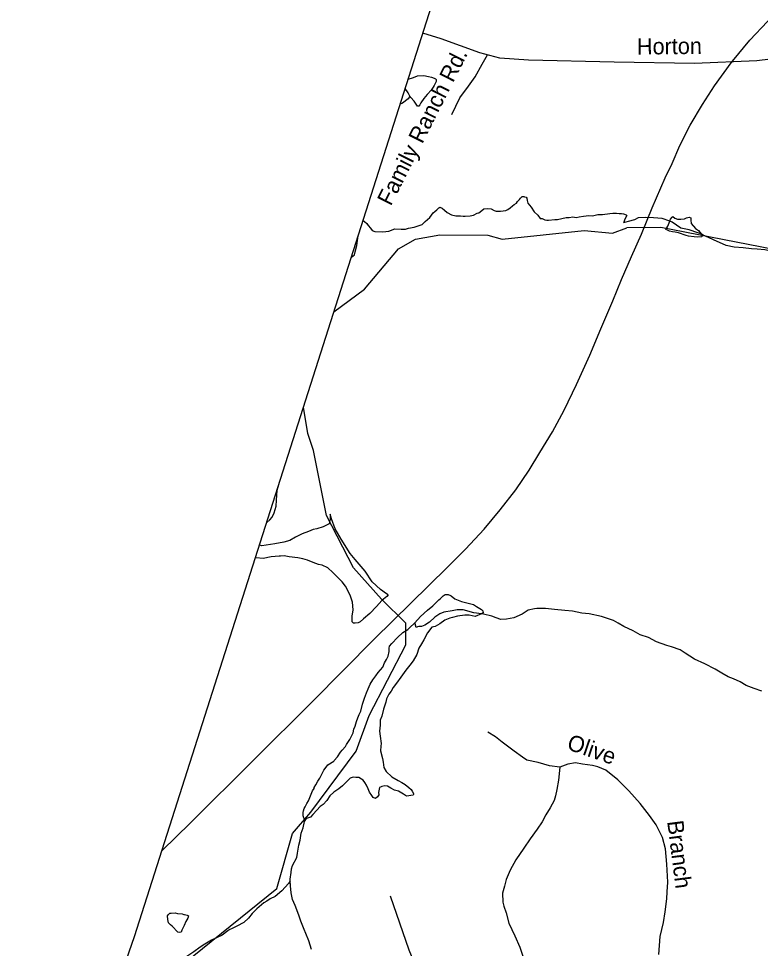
# Model space of a CAD drawing. Extents: x 2001466 to 2224147, y 644118 to 847247.
# Drawn here: x 2006818 to 2011176, y 697641 to 703106 of the extents above; entities that cross this region are included whole.
import ezdxf

# ---------------------------------------------------------------- set-up
doc = ezdxf.new("R2010")
doc.units = 0
for name, color, linetype in [('Exist Boundary Political CountyLine', 7, 'Continuous'), ('Exist Hydrographic Misc Water Feature', 7, 'Continuous'), ('Exist Railroad Mainline', 7, 'Continuous'), ('Exist Road Non-System Type 51', 7, 'Continuous'), ('Exist Road Non-System Type 51 Label', 7, 'Continuous'), ('Exist Road Secondary Type 51 Attributed', 7, 'Continuous'), ('Exist Road Secondary Type 51 Label', 7, 'Continuous')]:
    doc.layers.add(name, color=color, linetype=linetype)

msp = doc.modelspace()

# ---------------------------------------------------------------- linework, layer by layer
at = {"layer": 'Exist Boundary Political CountyLine'}
msp.add_lwpolyline([(2006817.6, 695750.4), (2007499.4, 697710.6), (2010412.6, 706844.6), (2011918.3, 711705.5), (2013748.8, 717730), (2014941.8, 722041.3), (2015284.7, 723238.9), (2015749.8, 724659.3), (2016152.8, 726117.8), (2016501.7, 727373.6), (2016860.6, 728619.5), (2017411.9, 730567.4), (2017756.8, 731851.4), (2018083.6, 732956.8), (2018350.2, 733869.6), (2018833.4, 735584.8), (2018918.2, 735898.3), (2019734.3, 740137.7), (2020502.6, 744108.1), (2021805.5, 746807.9), (2022821.6, 749625), (2023527, 751602.5)], dxfattribs=at)
at = {"layer": 'Exist Hydrographic Misc Water Feature'}
for p, q in [((2010307.7, 701844.5), (2010390.7, 701875.6)), ((2009092.7, 699552.7), (2008950.6, 699693.4))]:
    msp.add_line(p, q, dxfattribs=at)
for points in [[(2009106.6, 702749.8), (2009136.8, 702759.4), (2009160.8, 702769.4), (2009198.7, 702771.4), (2009224.8, 702765.5), (2009242.8, 702761.5), (2009258.8, 702755.5), (2009266.8, 702751.5), (2009270.7, 702747.5), (2009270.7, 702735.5), (2009258.8, 702713.5), (2009242.8, 702687.5), (2009218.8, 702659.5), (2009198.9, 702635.4), (2009180.9, 702611.5), (2009175, 702599.4), (2009168.8, 702591.4), (2009160.8, 702591.4), (2009140.9, 702621.4), (2009122.9, 702641.4), (2009116.9, 702649.4)], [(2009116.9, 702649.4), (2009106.9, 702669.5), (2009089.3, 702695.6)], [(2009116.9, 702649.4), (2009106.9, 702633.4), (2009072.8, 702609.4), (2009059.9, 702603.5)], [(2014407.7, 701337.8), (2014532.8, 701745.4), (2014532.8, 701896.4), (2014490.7, 701989), (2014390.7, 702096.1), (2014148.7, 702153.5), (2013665.6, 702120.7), (2013198.7, 702304.1), (2012782.6, 702260.1), (2012598.7, 702368.8), (2012440.6, 702345.7), (2012332.8, 702302.1), (2012082.8, 702103.7), (2011815.6, 702036.9), (2011507.6, 701793.8), (2011324.7, 701735.2), (2010590.6, 701878.2), (2010390.7, 701875.6)], [(2008841.7, 701919.2), (2008849.3, 701913.3), (2008863.3, 701901.3), (2008871.3, 701889.4), (2008885.4, 701873.3), (2008895.3, 701861.3), (2008911.3, 701855.3), (2008957.4, 701853.5), (2008993.3, 701857.4), (2009027.3, 701869.4), (2009065.2, 701867.4), (2009091.3, 701867.5), (2009107.3, 701873.5), (2009141.3, 701879.5), (2009189.3, 701895.5), (2009207.1, 701913.6), (2009233.2, 701937.6), (2009253.3, 701963.6), (2009263.1, 701971.6), (2009275.2, 701981.6), (2009279.1, 701985.6), (2009287.1, 701993.6), (2009293.3, 701997.6), (2009305.2, 701991.6), (2009319.3, 701979.6), (2009335.3, 701965.6), (2009361.1, 701951.6), (2009387.2, 701945.7), (2009413.2, 701945.7), (2009429.2, 701943.7), (2009441.1, 701943.7), (2009471.3, 701945.8), (2009489.3, 701949.8), (2009511.2, 701961.8), (2009521.3, 701963.8), (2009539.1, 701977.8), (2009551.2, 701987.8), (2009573.2, 701989.8), (2009593.3, 701987.8), (2009611.3, 701977.8), (2009623.2, 701973.8), (2009649, 701973.8), (2009679.2, 701977.8), (2009691.3, 701983.8), (2009705, 701993.9), (2009719.2, 702005.9), (2009729, 702013.9), (2009743.2, 702021.9), (2009749.1, 702029.9), (2009753, 702033.9), (2009761, 702041.9), (2009767.1, 702049.9), (2009771, 702053.9), (2009777, 702059.9), (2009785.2, 702059.9), (2009789.1, 702057.9), (2009799.1, 702055.9), (2009803, 702049.9), (2009805.1, 702035.9), (2009809.2, 702022), (2009829.1, 701998), (2009847.1, 701969.9), (2009867.2, 701949.9), (2009881.2, 701931.9), (2009893.2, 701930), (2009909, 701924), (2009921.1, 701922), (2009931.2, 701922), (2009967.3, 701926), (2009983.1, 701926), (2010009.1, 701930.1), (2010035.1, 701936.1), (2010043.1, 701936.1), (2010053, 701936.1), (2010073.1, 701940.1), (2010093.2, 701936.1), (2010111, 701940.1), (2010137.1, 701944.1), (2010167, 701948.1), (2010189.1, 701946.2), (2010221.1, 701954.2), (2010247.2, 701954.2), (2010291, 701960.2), (2010309.1, 701962.3), (2010331, 701962.3), (2010345, 701960.3), (2010359.1, 701960.3), (2010371, 701958.3), (2010387, 701952.3), (2010391.1, 701948.3), (2010381.1, 701930.2), (2010371, 701906.3)], [(2010643.1, 701914.5), (2010599, 701930.4), (2010547.2, 701934.4), (2010503.1, 701936.4), (2010457.1, 701934.3), (2010437, 701922.3), (2010399.1, 701912.4), (2010371, 701906.3)], [(2010643.1, 701914.5), (2010647, 701926.4), (2010657.1, 701938.4), (2010661.2, 701942.4), (2010673.1, 701932.4), (2010689.1, 701926.4), (2010709.2, 701926.5), (2010729, 701928.4), (2010741.1, 701934.5), (2010749.1, 701936.5), (2010757.1, 701938.5), (2010767, 701934.5), (2010767, 701920.5), (2010769, 701902.5), (2010795.1, 701872.5), (2010811.1, 701860.6), (2010819.1, 701850.6), (2010829.1, 701838.6)], [(2010829.1, 701838.6), (2010831.2, 701830.6), (2010831.2, 701822.6), (2010809, 701820.5), (2010787.1, 701822.5), (2010753, 701826.5), (2010739.1, 701830.5), (2010695, 701846.5), (2010675.1, 701850.5), (2010659.1, 701852.5), (2010641.1, 701856.5), (2010629, 701862.5), (2010621, 701866.5), (2010631, 701886.5), (2010643.1, 701914.5)], [(2010829.1, 701838.6), (2010807.2, 701846.5), (2010757.1, 701864.5), (2010709.2, 701874.5), (2010683.1, 701892.5), (2010657.1, 701908.5), (2010643.1, 701914.5)], [(2008670.3, 701382), (2008849.7, 701516.5), (2009049.7, 701752), (2009149.7, 701809), (2009291.6, 701835.7), (2009574.8, 701833.2), (2009657.6, 701808.5), (2010140.7, 701861), (2010307.7, 701844.5)], [(2008771.6, 701699.4), (2008781.5, 701709.3), (2008791.5, 701717.3), (2008795.4, 701735.3), (2008805.2, 701771.3), (2008809.3, 701801.3), (2008813.1, 701829.6)], [(2011523, 701743), (2011517.1, 701743), (2011459, 701739), (2011405.1, 701740.9), (2011357.1, 701740.9), (2011329, 701736.9), (2011279, 701732.8), (2011247, 701736.8), (2011201.1, 701746.8), (2011157, 701750.8), (2011123.2, 701752.8), (2011075, 701758.7), (2011021, 701762.7), (2010975.1, 701772.7), (2010901.1, 701804.6), (2010871.1, 701818.6), (2010839.2, 701832.6), (2010829.1, 701838.6)], [(2008950.6, 699693.4), (2008784.7, 699877.3), (2008625.6, 700185.7), (2008550.8, 700567.8), (2008516.7, 700666.9), (2008491.7, 700821.9)], [(2008275.5, 700144.1), (2008294.5, 700159.2), (2008306.4, 700175.1), (2008318.4, 700201.1), (2008330.3, 700239.2), (2008332.4, 700275.2), (2008334.2, 700303.2), (2008336.1, 700334), (2008340.3, 700347.3), (2008344, 700358.7)], [(2008648.4, 700193.4), (2008648.4, 700163.4), (2008642.2, 700135.4), (2008606.3, 700119.4), (2008570.5, 700107.3), (2008548.3, 700103.3), (2008520.4, 700091.3), (2008484.3, 700077.3), (2008444.4, 700057.3), (2008410.3, 700039.3), (2008376.5, 700029.2), (2008322.3, 700019.2), (2008246.5, 700007.2), (2008232.8, 700010.3)], [(2008988.6, 699719.7), (2008978.5, 699725.7), (2008944.5, 699749.7), (2008894.4, 699795.6), (2008854.5, 699857.5), (2008794.4, 699927.5), (2008766.5, 699961.5), (2008712.4, 700045.4), (2008678.3, 700107.4), (2008656.4, 700165.4), (2008648.4, 700193.4)], [(2008988.6, 699719.7), (2008980.6, 699709.7), (2008952.5, 699685.6), (2008920.5, 699649.6), (2008880.7, 699609.6), (2008844.6, 699577.6), (2008824.7, 699559.6), (2008812.6, 699553.5), (2008794.6, 699551.5), (2008784.7, 699551.5), (2008776.7, 699559.5), (2008776.7, 699593.5), (2008782.7, 699631.6), (2008778.6, 699675.5), (2008766.5, 699717.5), (2008756.4, 699735.5), (2008748.4, 699751.5), (2008738.6, 699769.5), (2008718.5, 699795.5), (2008688.6, 699825.5), (2008664.6, 699849.4), (2008634.4, 699877.4), (2008600.6, 699893.4), (2008580.5, 699897.4), (2008548.5, 699909.4), (2008514.5, 699923.3), (2008488.4, 699931.3), (2008458.5, 699937.3), (2008406.6, 699943.3), (2008378.5, 699947.3), (2008356.6, 699947.2), (2008348.6, 699947.2), (2008300.6, 699943.2), (2008254.5, 699933.1), (2008212.4, 699937.1)], [(2009144.6, 699553.8), (2009178.6, 699591.8), (2009220.5, 699629.8), (2009250.6, 699653.9), (2009270.5, 699673.8), (2009286.5, 699689.8), (2009296.5, 699697.8), (2009312.5, 699713.9), (2009324.4, 699721.9), (2009340.4, 699721.9), (2009354.6, 699715.9), (2009358.5, 699713.9), (2009380.6, 699695.9), (2009420.6, 699679.9), (2009458.5, 699670), (2009490.5, 699662), (2009508.6, 699650), (2009526.6, 699638), (2009536.5, 699632), (2009544.5, 699624.1), (2009546.5, 699614), (2009536.5, 699608)], [(2011184.7, 699153.1), (2011138.5, 699169.1), (2011092.6, 699187), (2011056.7, 699207), (2011018.6, 699224.9), (2010986.6, 699236.9), (2010948.7, 699259), (2010910.7, 699282.9), (2010848.6, 699312.9), (2010788.5, 699340.8), (2010734.6, 699376.8), (2010704.4, 699394.8), (2010652.6, 699412.7), (2010626.5, 699420.8), (2010564.6, 699442.7), (2010518.5, 699468.6), (2010468.4, 699484.6), (2010428.4, 699506.6), (2010372.5, 699532.6), (2010340.5, 699552.5), (2010312.6, 699568.5), (2010242.5, 699592.5), (2010170.5, 699606.4), (2010126.6, 699610.4), (2010072.5, 699622.4), (2010026.5, 699626.3), (2009966.5, 699632.3), (2009912.5, 699638.3), (2009862.5, 699638.2), (2009848.5, 699636.3), (2009810.6, 699628.2), (2009776.6, 699606.2), (2009726.5, 699584.1), (2009684.5, 699576.1), (2009650.5, 699574.1), (2009622.6, 699584), (2009598.6, 699594), (2009548.6, 699606.1), (2009536.5, 699608)], [(2009536.5, 699608), (2009500.6, 699592), (2009464.5, 699600), (2009438.4, 699599.9), (2009396.6, 699593.9), (2009366.5, 699585.9), (2009350.5, 699581.9), (2009322.6, 699569.9), (2009292.7, 699547.8), (2009264.6, 699533.8), (2009244.7, 699529.9), (2009220.7, 699495.9), (2009198.7, 699453.8), (2009184.6, 699431.8), (2009168.8, 699405.8), (2009156.7, 699367.8), (2009134.8, 699331.8), (2009116.7, 699305.8), (2009092.7, 699275.8), (2009082.7, 699261.8), (2009062.8, 699235.8), (2009037, 699199.7), (2009018.9, 699173.7), (2009006.8, 699153.7), (2008992.9, 699135.7), (2008978.9, 699107.8), (2008974.8, 699087.7), (2008960.9, 699047.7), (2008951, 699005.7), (2008941, 698981.7), (2008941, 698953.7), (2008937.1, 698917.7), (2008941, 698887.7), (2008947.1, 698845.7), (2008945.1, 698829.8), (2008943, 698801.7), (2008955.1, 698757.7), (2008959, 698735.8), (2008963.1, 698703.7), (2008977.1, 698679.8), (2009011.1, 698649.8), (2009047.2, 698627.9), (2009069.1, 698615.8), (2009089, 698603.8), (2009111.2, 698585.8), (2009123.1, 698575.8), (2009129.2, 698565.9), (2009137.2, 698551.9), (2009137.2, 698545.9), (2009135.2, 698541.9), (2009097.2, 698535.9), (2009079.2, 698547.9), (2009049.3, 698565.9), (2009025.3, 698571.8), (2009005.2, 698581.8), (2008985.3, 698593.8), (2008969.3, 698595.8), (2008951.2, 698591.7), (2008947.1, 698589.8), (2008937.3, 698585.8), (2008931.1, 698557.8), (2008933.2, 698543.7), (2008925.2, 698531.7), (2008915.2, 698521.7), (2008901.2, 698527.7), (2008893.2, 698539.7), (2008879.3, 698559.7), (2008871.3, 698579.7), (2008861.2, 698599.7), (2008851.2, 698615.7), (2008841.1, 698629.7), (2008831.3, 698635.7), (2008817.3, 698645.7), (2008799.1, 698645.7), (2008783.3, 698647.7), (2008765.3, 698641.7), (2008739.2, 698615.6), (2008721.2, 698595.6), (2008699.2, 698579.6), (2008669.3, 698559.6), (2008645.3, 698537.6), (2008629.3, 698509.6), (2008607.2, 698487.5), (2008589.3, 698475.5), (2008569.4, 698453.5), (2008545.4, 698427.5), (2008533.3, 698411.5), (2008509.4, 698403.6)], [(2009536.5, 699608), (2009492.6, 699614), (2009428.6, 699629.9), (2009394.6, 699629.9), (2009364.4, 699625.9), (2009316.4, 699617.9), (2009292.4, 699607.9), (2009262.7, 699587.9), (2009230.7, 699557.8), (2009204.7, 699539.8), (2009184.6, 699533.8), (2009168.6, 699533.8), (2009160.6, 699531.8), (2009152.6, 699527.8)], [(2008509.4, 698403.6), (2008495.4, 698401.6), (2008489.5, 698419.5), (2008489.5, 698439.5), (2008491.3, 698449.5), (2008495.4, 698463.5), (2008501.4, 698473.5), (2008511.4, 698493.5), (2008521.2, 698507.5), (2008533.3, 698537.6), (2008545.2, 698567.5), (2008553.2, 698581.5), (2008553.2, 698587.5), (2008563.3, 698601.5), (2008575.2, 698623.5), (2008587.3, 698641.5), (2008597.3, 698661.6), (2008611.3, 698687.5), (2008619.1, 698697.5), (2008635, 698719.5), (2008669.1, 698741.5), (2008671.1, 698745.5), (2008691, 698767.5), (2008709.1, 698793.6), (2008719.1, 698805.6), (2008737.2, 698827.6), (2008743.1, 698839.6), (2008763, 698869.6), (2008775.1, 698891.6), (2008783.1, 698907.7), (2008787, 698929.6), (2008795, 698947.6), (2008803, 698973.6), (2008811, 698995.6), (2008819, 699015.7), (2008829, 699035.7), (2008838.9, 699075.7), (2008848.9, 699111.6), (2008860.8, 699143.7), (2008870.9, 699165.7), (2008876.8, 699179.7), (2008883, 699193.7), (2008899, 699219.7), (2008916.8, 699243.6), (2008930.7, 699261.6), (2008956.8, 699293.7), (2008966.8, 699319.7), (2008978.7, 699339.7), (2008988.8, 699357.7), (2008994.7, 699385.6), (2008994.7, 699405.7), (2008996.8, 699417.7), (2009010.7, 699433.7), (2009044.5, 699467.7), (2009074.7, 699497.7), (2009104.6, 699515.8), (2009118.6, 699529.8), (2009140.7, 699549.7), (2009144.6, 699553.8)], [(2008534.6, 698441.9), (2008801.6, 698800.7), (2008876.6, 699009.2), (2009092.7, 699424.8), (2009092.7, 699552.7)], [(2009152.6, 699527.8), (2009146.7, 699547.8), (2009144.6, 699553.8)], [(2007643.6, 697216.5), (2007660.6, 697377), (2007735.7, 697509.9), (2008335.7, 697993.2), (2008426.5, 698316.2), (2008534.6, 698441.9)], [(2008413.6, 698037.5), (2008413.6, 698047.5), (2008419.5, 698087.5), (2008421.6, 698109.5), (2008427.5, 698127.4), (2008451.5, 698175.5), (2008455.4, 698201.5), (2008463.4, 698247.5), (2008471.4, 698277.5), (2008477.6, 698317.5), (2008489.5, 698349.5), (2008497.5, 698387.5), (2008509.4, 698403.6)], [(2008413.6, 698037.5), (2008403.5, 698021.5), (2008363.6, 697979.5), (2008325.6, 697945.4), (2008295.7, 697931.5), (2008275.6, 697919.4), (2008257.8, 697909.4), (2008217.8, 697873.4), (2008189.7, 697845.3), (2008167.7, 697819.4), (2008141.7, 697793.3), (2008099.9, 697771.3), (2008067.9, 697755.3), (2008057.8, 697751.3), (2008047.8, 697743.3)], [(2008537.9, 697633.6), (2008523.7, 697685.6), (2008505.7, 697727.6), (2008495.8, 697751.6), (2008475.7, 697801.5), (2008463.6, 697835.5), (2008441.7, 697893.5), (2008427.5, 697927.5), (2008419.5, 697967.5), (2008415.6, 698009.4), (2008413.6, 698037.5)], [(2007789.8, 697775.1), (2007779.8, 697755.1), (2007775.9, 697747.1), (2007771.8, 697737.1), (2007763.8, 697735.1), (2007753.9, 697737.1), (2007719.9, 697771.1), (2007709.9, 697779.1), (2007697.8, 697791.1), (2007693.9, 697811.1), (2007691.8, 697833.1), (2007697.8, 697841.1), (2007705.8, 697847.1), (2007713.8, 697847.1), (2007737.7, 697849.1), (2007751.9, 697845.1), (2007777.7, 697843.1), (2007787.8, 697841.1), (2007791.7, 697841.1), (2007807.7, 697837.1), (2007815.9, 697833.1), (2007811.8, 697819.2), (2007799.9, 697799.2), (2007789.8, 697775.1)], [(2008047.8, 697743.3), (2008013.9, 697719.3), (2007951.8, 697689.2), (2007911.8, 697665.2), (2007883.9, 697647.2), (2007847.9, 697621.1), (2007817.9, 697601.1), (2007799.9, 697589.1), (2007782, 697565.1)]]:
    msp.add_lwpolyline(points, dxfattribs=at)
at = {"layer": 'Exist Railroad Mainline'}
for points in [[(2011011.5, 702855.5), (2011112.7, 702979.6), (2011218.3, 703087.9), (2011331.9, 703202.4)], [(2007660.6, 698216.1), (2007824.9, 698377.8), (2008199.8, 698749.2), (2008542.5, 699090.4), (2008909.1, 699459.8), (2009335.7, 699879.4), (2009443.3, 699987.8), (2009552.9, 700104.2), (2009646.4, 700218.5), (2009738.1, 700336.8), (2009817.6, 700451), (2009879.1, 700555.2), (2009954.8, 700677.4), (2010022.4, 700803.7), (2010095.7, 700956), (2010173.2, 701128.2), (2010238.6, 701282.5), (2010308.2, 701446.7), (2010359.7, 701572.9), (2010419.1, 701707.1), (2010476.8, 701839.3), (2010540.1, 701993.6), (2010615.5, 702169.9), (2010657.3, 702254.1), (2010702.8, 702360.1), (2010762.5, 702480.3), (2010835.9, 702600.6), (2010905.6, 702710.8), (2011003.1, 702845.3), (2011011.5, 702855.5)]]:
    msp.add_lwpolyline(points, dxfattribs=at)
at = {"layer": 'Exist Road Non-System Type 51'}
for points in [[(2009363.5, 702542.1), (2009410.8, 702639.9), (2009461.2, 702708), (2009499.7, 702764.3), (2009541.1, 702838.4), (2009573.3, 702892)], [(2009996.4, 698705.4), (2009936.3, 698713.2), (2009870.3, 698733.2), (2009804.4, 698746.9), (2009777.4, 698765), (2009729.3, 698800.1), (2009659.2, 698852.7), (2009619.8, 698883.4), (2009574, 698912.4)], [(2009996.4, 698705.4), (2009988.6, 698629.4), (2009980.7, 698575.5), (2009971, 698537.3), (2009965, 698509.4), (2009941.1, 698467.3), (2009915.1, 698425.2), (2009893.2, 698385.3), (2009863.3, 698341.1), (2009823.6, 698285.1), (2009785.7, 698229.1), (2009737.9, 698160.8), (2009706, 698100.9), (2009682.1, 698046.8), (2009672.3, 698006.8), (2009660.2, 697964.6), (2009662.4, 697912.8), (2009668.5, 697888.6), (2009682.5, 697850.7), (2009698.7, 697788.8), (2009733, 697714.9), (2009763, 697648.9), (2009791.2, 697559.1)], [(2010579.4, 697604.9), (2010586.7, 697711.1), (2010606.6, 697793.1), (2010616.3, 697855.1), (2010626.3, 697933.1), (2010627.7, 697973.3), (2010632.3, 698030.9), (2010625.4, 698136.8), (2010618.5, 698226.7), (2010600.1, 698293.5), (2010563.2, 698367.2), (2010524.1, 698422.5), (2010468.8, 698491.6), (2010402.1, 698567.7), (2010337.6, 698632.2), (2010268.5, 698687.5), (2010219.8, 698708.1), (2010189.2, 698716.8), (2010130.4, 698723.9), (2010090.3, 698731.7), (2010044.4, 698723.6), (2009996.4, 698705.4)], [(2009545.6, 696274.6), (2009490.9, 696361), (2009466.8, 696416.1), (2009442.8, 696464.3), (2009411.8, 696540), (2009377.4, 696684.6), (2009281.1, 697225), (2009112.5, 697631.2), (2009002.4, 697947.9)]]:
    msp.add_lwpolyline(points, dxfattribs=at)
at = {"layer": 'Exist Road Secondary Type 51 Attributed'}
msp.add_lwpolyline([(2011459.3, 702895.1), (2011154.6, 702856.8), (2010789.2, 702842.4), (2010317.4, 702849.6), (2009814, 702862.4), (2009644.1, 702873.5), (2009527.6, 702903.9), (2009301.1, 702986.9), (2009192.7, 703019.9)], dxfattribs=at)

# ---------------------------------------------------------------- texts
at = {"layer": 'Exist Road Non-System Type 51 Label'}
for s, rotation, p in [('Family Ranch Rd.', 63.2453, (2009004.2, 702000)), ('Olive', 341.0561, (2010033.2, 698813)), ('Branch', 277.2245, (2010627.7, 698387.6))]:
    msp.add_text(s, height=95, rotation=rotation, dxfattribs=at).set_placement(p)
at = {"layer": 'Exist Road Secondary Type 51 Label'}
msp.add_text('Horton', height=95, rotation=0.6443, dxfattribs=at).set_placement((2010450.9, 702894.3))

doc.saveas('drawing.dxf')
